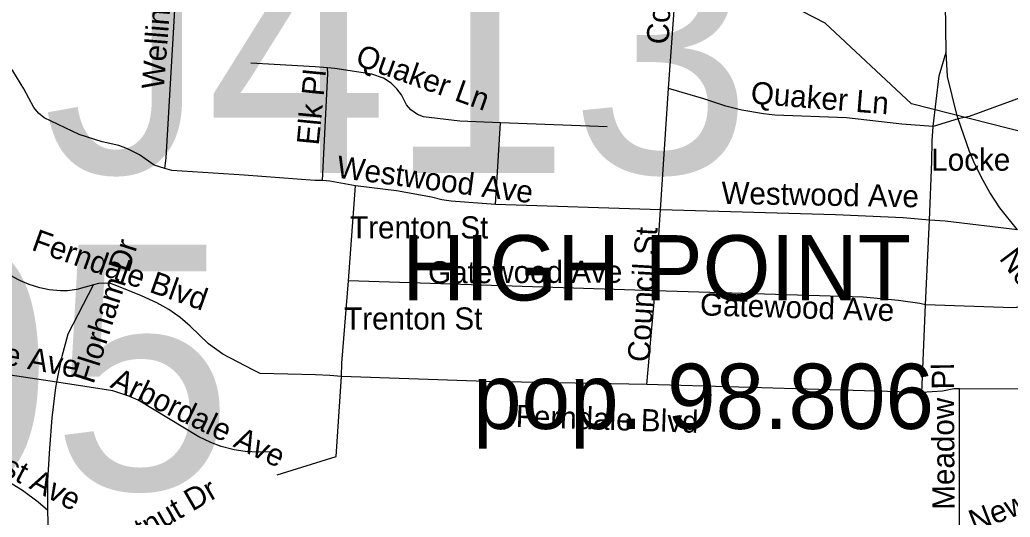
# Model space of a CAD drawing. Extents: x 1662474 to 1856135, y 779280 to 917889.
# Drawn here: x 1695531 to 1699781, y 804609 to 806742 of the extents above; entities that cross this region are included whole.
import ezdxf

# ---------------------------------------------------------------- set-up
doc = ezdxf.new("R2010")
doc.units = 0
for name, color, linetype in [('Exist Civil Demographics City Label', 7, 'Continuous'), ('Exist Civil Demographics City Population Label', 7, 'Continuous'), ('Exist Hydrographic Misc Water Feature', 7, 'Continuous'), ('Exist Road Non-System Structure Non-Sys Other Number Label', 7, 'Continuous'), ('Exist Road Non-System Type 51', 7, 'Continuous'), ('Exist Road Non-System Type 51 Label', 7, 'Continuous')]:
    doc.layers.add(name, color=color, linetype=linetype)

msp = doc.modelspace()

# ---------------------------------------------------------------- linework, layer by layer
at = {"layer": 'Exist Hydrographic Misc Water Feature'}
msp.add_lwpolyline([(1699948, 806232.5), (1699358, 806382.4), (1698986.9, 806728), (1698746, 806854.4)], dxfattribs=at)
at = {"layer": 'Exist Road Non-System Type 51'}
for p, q in [((1699506.9, 806603.8), (1699503.4, 806813.5)), ((1698280.4, 805926.9), (1698315.2, 806447.1)), ((1697573, 805950.5), (1697593.8, 806300.9)), ((1698051.8, 806283), (1697593.8, 806300.9)), ((1699558.2, 806317.7), (1699451.1, 806284.4)), ((1696941.5, 805623.2), (1696971.6, 806030.2)), ((1698280.4, 805926.9), (1697573, 805950.5)), ((1698256.9, 805580.2), (1698280.4, 805926.9)), ((1699417.6, 805519.2), (1699434.9, 805882.8)), ((1698256.9, 805580.2), (1696941.5, 805623.2)), ((1698222.1, 805178.1), (1698256.9, 805580.2)), ((1699402.4, 805143.9), (1699417.6, 805519.2)), ((1699402.4, 805143.9), (1698222.1, 805178.1)), ((1699852.5, 805158.7), (1699563.8, 805160.2))]:
    msp.add_line(p, q, dxfattribs=at)
for points in [[(1696153.4, 806104), (1696158.4, 806149.7), (1696225.2, 807273.9)], [(1698315.2, 806447.1), (1698362.1, 807100.1), (1698367.1, 807207.2), (1698364, 807254.9)], [(1699451.1, 806284.4), (1699476.9, 806501.4), (1699506.9, 806603.8)], [(1699558.2, 806317.7), (1699551.6, 806336.4), (1699512.4, 806498.5), (1699506.9, 806603.8)], [(1696153.4, 806104), (1696107.4, 806118.8), (1696044.4, 806162.6), (1695992.6, 806189.4), (1695955.9, 806202.8), (1695884.4, 806219), (1695785.9, 806250.2), (1695635.5, 806321.9), (1695611.4, 806341.6), (1695591.6, 806365.7), (1695548.1, 806446.6), (1695500.6, 806522.9), (1695485.4, 806536), (1695467, 806543.9), (1695440.2, 806545), (1695388.2, 806528.9), (1695328.4, 806504.9), (1695271.4, 806475.4), (1695227.1, 806445.5), (1695177, 806404.9), (1695136, 806364.7), (1695105.1, 806326.4)], [(1696851.5, 806535.8), (1696798.4, 806540.8), (1696521.6, 806556)], [(1696829.6, 806053.4), (1696853.4, 806512.2), (1696851.5, 806535.8)], [(1697593.8, 806300.9), (1697418.6, 806308), (1697262.8, 806325.6), (1697237, 806336.4), (1697208.9, 806356.5), (1697190.9, 806378), (1697168.2, 806420), (1697148.6, 806446.9), (1697124.6, 806469.9), (1697091.1, 806491.7), (1697041, 806509), (1696883.2, 806533.7), (1696851.5, 806535.8)], [(1699451.1, 806284.4), (1699316.5, 806294.9), (1699078.1, 806322.4), (1698770.9, 806332.9), (1698722.9, 806338.9), (1698629.9, 806355.5), (1698561.1, 806371.8), (1698466.1, 806403.5), (1698315.2, 806447.1)], [(1699914.4, 806441), (1699605.2, 806327.4), (1699558.2, 806317.7)], [(1699812.9, 805841.1), (1699737.2, 805936.1), (1699693.9, 806001.4), (1699664.5, 806052.6), (1699629.6, 806122.9), (1699606.5, 806177), (1699558.2, 806317.7)], [(1699434.9, 805882.8), (1699445.4, 806135), (1699445.6, 806222.9), (1699451.1, 806284.4)], [(1695847.2, 805605.4), (1695775.4, 805585.9), (1695736, 805580.2), (1695705.6, 805579.4), (1695657.2, 805584.6), (1695617.4, 805592.5), (1695570.9, 805606.4), (1695533.6, 805622.2), (1695497.4, 805640.8), (1695451.2, 805679.9), (1695427.9, 805706.4), (1695407.1, 805735), (1695389.9, 805765.8), (1695375.6, 805797.8), (1695365.4, 805829.5), (1695291.4, 805907.4), (1695255.1, 805938.4), (1695228.9, 805957.4), (1695144.9, 805998), (1695112.9, 806020.6), (1695080.6, 806054.2), (1695056, 806094.4), (1695048.1, 806102.2)], [(1696494, 806075.4), (1696183, 806095.9), (1696153.4, 806104)], [(1696829.6, 806053.4), (1696796.9, 806052.9), (1696494, 806075.4)], [(1696971.6, 806030.2), (1696862, 806050.5), (1696829.6, 806053.4)], [(1697573, 805950.5), (1697381.4, 805964.9), (1697342.5, 805970.2), (1697297.6, 805981.2), (1697146.8, 806008.8), (1696971.6, 806030.2)], [(1699434.9, 805882.8), (1699322.2, 805893), (1699031.2, 805905.4), (1698280.4, 805926.9)], [(1699812.9, 805841.1), (1699501.9, 805878.4), (1699434.9, 805882.8)], [(1696530.2, 805241.6), (1696402.6, 805308.2), (1696340.1, 805352.4), (1696262, 805429), (1696219.5, 805466.2), (1696170.4, 805499.6), (1696119.1, 805527.9), (1696053.6, 805557.9), (1695940.5, 805604.9), (1695919.5, 805611.4), (1695897.6, 805613.2), (1695868.9, 805611.4), (1695847.2, 805605.4)], [(1696911.6, 805211.9), (1696912.4, 805269.7), (1696941.5, 805623.2)], [(1699985.5, 805615.4), (1699860.1, 805527.2), (1699833.6, 805515.1), (1699808.1, 805508.2), (1699792.6, 805506.4), (1699417.6, 805519.2)], [(1695690.1, 805188), (1695710.6, 805294.1), (1695738.6, 805396.2), (1695847.2, 805605.4)], [(1699417.6, 805519.2), (1699393.1, 805525.4), (1699302.1, 805538.2), (1699149.6, 805553.4), (1698256.9, 805580.2)], [(1695690.1, 805188), (1695248.4, 805253.9), (1695179.6, 805271.2), (1695109.8, 805293.9), (1695043.1, 805318.5), (1694959.1, 805359.2), (1694892.8, 805378.9), (1694796.1, 805389.4), (1694765.9, 805384.9), (1694737.4, 805373.9)], [(1696911.6, 805211.9), (1696862, 805217.4), (1696799.8, 805220.1), (1696561.8, 805225.1), (1696530.2, 805241.6)], [(1695650.6, 804637.7), (1695651.8, 804767.4), (1695659.4, 804904.1), (1695670.4, 805035.9), (1695685.4, 805165.5), (1695690.1, 805188)], [(1696612.1, 804889.6), (1696554.9, 804887.5), (1696497.4, 804891.2), (1696450.4, 804898), (1696395.4, 804912.4), (1696350.9, 804928.8), (1696299.2, 804953.7), (1696038.1, 805111.7), (1695999, 805128.4), (1695929.4, 805151), (1695690.1, 805188)], [(1696636, 804790.2), (1696888.2, 804869.7), (1696911.6, 805211.9)], [(1698222.1, 805178.1), (1697530.1, 805191.8), (1696911.6, 805211.9)], [(1699563.8, 805160.2), (1699538.6, 805160.2), (1699490, 805150), (1699402.4, 805143.9)], [(1699556.9, 804487.5), (1699564.2, 804530.6), (1699563.8, 805160.2)], [(1695650.6, 804637.7), (1695610.2, 804673.9), (1695542.4, 804722.9), (1695396.9, 804812.2), (1695265.6, 804868.6), (1695155.4, 804898.9), (1695095.6, 804912.2), (1694986.4, 804926.1), (1694959.4, 804922.2), (1694935.2, 804907.2)], [(1695678.2, 804272.6), (1695654.1, 804538.2), (1695650.6, 804637.7)]]:
    msp.add_lwpolyline(points, dxfattribs=at)

# ---------------------------------------------------------------- texts
at = {"layer": 'Exist Civil Demographics City Label'}
msp.add_text('HIGH POINT', height=280, dxfattribs=at).set_placement((1697171.4, 805538.7))
at = {"layer": 'Exist Civil Demographics City Population Label'}
msp.add_text('pop. 98.806', height=280, dxfattribs=at).set_placement((1697476.1, 804987.5))
at = {"layer": 'Exist Road Non-System Structure Non-Sys Other Number Label'}
for s, p in [('J413', (1695629.2, 806084.9)), ('J405', (1693402.7, 804727.4))]:
    msp.add_text(s, height=1049.86, dxfattribs=at).set_placement(p)
at = {"layer": 'Exist Road Non-System Type 51 Label'}
for s, rotation, p in [('Wellington St', 85.4039, (1696148.2, 806441.8)), ('Council St', 87.4553, (1698315.6, 806635.7)), ('Quaker Ln', 340.3315, (1696966, 806550.5)), ('Elk Pl', 84.4008, (1696813.6, 806201.8)), ('Quaker Ln', 355.4561, (1698665.3, 806383.6)), ('Westwood Ave', 352.4999, (1696886.7, 806065.9)), ('Westwood Ave', 358.9619, (1698541.4, 805953.2)), ('Ferndale Blvd', 340.3862, (1695576.5, 805756.7)), ('Council St', 86.6355, (1698234.1, 805272.5)), ('Florham Dr', 72.3593, (1695846.9, 805176.9)), ('North Lindsay St', 306.8541, (1699731.1, 805718.3)), ('Gatewood Ave', 0.2365, (1697283.3, 805611.6)), ('Gatewood Ave', 358.2688, (1698449, 805474.9)), ('Arbordale Ave', 349.2989, (1694984.4, 805354.8)), ('Arbordale Ave', 334.3265, (1695914.4, 805167.9)), ('Meadow Pl', 90.3243, (1699542.8, 804641.3)), ('Oakhurst Ave', 332.3954, (1695078.8, 804990)), ('Ferndale Blvd', 358.1091, (1697658.3, 804996.4)), ('Newton Pl', 21.1623, (1699626.5, 804544)), ('Chestnut Dr', 30.0474, (1695800.6, 804360))]:
    msp.add_text(s, height=95, rotation=rotation, dxfattribs=at).set_placement(p)
for s, p in [('Locke St', (1699442.5, 806095.2)), ('Trenton St', (1696948.3, 805804.4)), ('Trenton St', (1696922.8, 805413.8))]:
    msp.add_text(s, height=95, dxfattribs=at).set_placement(p)

doc.saveas('drawing.dxf')
